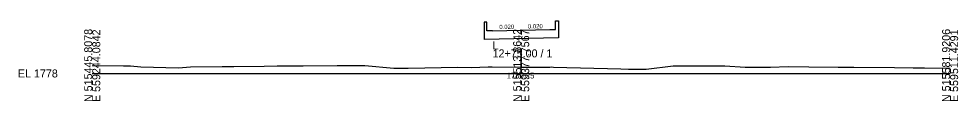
# Model space of a CAD drawing. Extents: x -26 to 1303, y -10 to 9545.
# Drawn here: x -25.7 to 302.8, y 7490.3 to 7518.4 of the extents above; entities that cross this region are included whole.
import ezdxf

# ---------------------------------------------------------------- set-up
doc = ezdxf.new("R2010")
doc.units = 0
for name, color, linetype in [('Exist Cross Section Cell', 7, 'Continuous'), ('Exist XS Center Line Elevation Label', 7, 'Continuous'), ('Exist XS Ground Line', 7, 'Continuous'), ('Prop XS Bridge', 7, 'Continuous'), ('Prop XS Dump Level', 7, 'Continuous'), ('Prop XS SE Text', 7, 'Continuous')]:
    doc.layers.add(name, color=color, linetype=linetype)

msp = doc.modelspace()

# ---------------------------------------------------------------- linework, layer by layer
at = {"layer": 'Exist Cross Section Cell'}
for p, q in [((150, 7500), (150, 7508.43)), ((0, 7500), (150, 7500)), ((150, 7500), (300, 7500))]:
    msp.add_line(p, q, dxfattribs=at)
at = {"layer": 'Exist XS Ground Line'}
for p, q in [((0, 7502.81), (10.9, 7502.62)), ((10.9, 7502.62), (11.85, 7502.63)), ((11.85, 7502.63), (13.37, 7502.67)), ((13.37, 7502.67), (17.03, 7502.37)), ((17.03, 7502.37), (30.18, 7502.03)), ((30.18, 7502.03), (34.39, 7502.38)), ((34.39, 7502.38), (45.4, 7502.41)), ((45.4, 7502.41), (49.52, 7502.46)), ((49.52, 7502.46), (60.12, 7502.59)), ((60.12, 7502.59), (64.72, 7502.63)), ((64.72, 7502.63), (73.71, 7502.7)), ((73.71, 7502.7), (85.63, 7502.74)), ((85.63, 7502.74), (92.47, 7502.77)), ((92.47, 7502.77), (95.27, 7502.76)), ((95.27, 7502.76), (105.43, 7501.81)), ((105.43, 7501.81), (106.79, 7501.84)), ((106.79, 7501.84), (110.44, 7501.91)), ((110.44, 7501.91), (127.84, 7502.25)), ((127.84, 7502.25), (132.57, 7502.13)), ((132.57, 7502.13), (138.4, 7502.27)), ((138.4, 7502.27), (139.9, 7502.27)), ((139.9, 7502.27), (150, 7502.25)), ((150, 7502.25), (160.05, 7502.23)), ((160.05, 7502.23), (160.64, 7502.28)), ((160.64, 7502.28), (161.33, 7502.22)), ((161.33, 7502.22), (184.9, 7501.59)), ((184.9, 7501.59), (187.48, 7501.56)), ((187.48, 7501.56), (190.33, 7501.51)), ((190.33, 7501.51), (193.72, 7501.46)), ((193.72, 7501.46), (203.14, 7502.69)), ((203.14, 7502.69), (208.72, 7502.62)), ((208.72, 7502.62), (212.5, 7502.65)), ((212.5, 7502.65), (215.74, 7502.62)), ((215.74, 7502.62), (221.26, 7502.63)), ((221.26, 7502.63), (228.28, 7502.23)), ((228.28, 7502.23), (232.19, 7502.2)), ((232.19, 7502.2), (237.15, 7502.17)), ((237.15, 7502.17), (243.39, 7502.4)), ((243.39, 7502.4), (250.56, 7502.33)), ((250.56, 7502.33), (260.81, 7502.19)), ((260.81, 7502.19), (266.35, 7502.15)), ((266.35, 7502.15), (280.57, 7502.06)), ((280.57, 7502.06), (287.14, 7501.96)), ((287.14, 7501.96), (291.08, 7501.93)), ((291.08, 7501.93), (300, 7501.87))]:
    msp.add_line(p, q, dxfattribs=at)
at = {"layer": 'Prop XS Bridge'}
for p, q in [((137, 7517.94), (137, 7514.94)), ((138, 7517.94), (137, 7517.94)), ((138, 7514.94), (138, 7517.94)), ((162, 7515.42), (162, 7518.42)), ((162, 7518.42), (163, 7518.42)), ((163, 7518.42), (163, 7515.42)), ((137, 7514.94), (137, 7511.94)), ((140, 7514.98), (138, 7514.94)), ((140, 7514.98), (150, 7515.18)), ((150, 7515.18), (160, 7515.38)), ((160, 7515.38), (162, 7515.42)), ((163, 7515.42), (163, 7512.42)), ((163, 7512.42), (137, 7511.94))]:
    msp.add_line(p, q, dxfattribs=at)
at = {"layer": 'Prop XS Dump Level'}
for p, q in [((140, 7514.98), (150, 7515.18)), ((150, 7515.18), (160, 7515.38))]:
    msp.add_line(p, q, dxfattribs=at)

# ---------------------------------------------------------------- texts
at = {"layer": 'Exist Cross Section Cell'}
for s, p in [('N 515445.8078', (0, 7490)), ('E 559244.0842', (2.8, 7490)), ('N 515513.8642', (150, 7490)), ('E 559377.7567', (152.8, 7490)), ('N 515581.9206', (300, 7490)), ('E 559511.4291', (302.8, 7490))]:
    msp.add_text(s, height=2.8, rotation=90, dxfattribs=at).set_placement(p)
for s, p in [('L', (140, 7508.43)), ('12+75.00 / 1', (140, 7505.63)), ('EL 1778', (-26, 7498.6))]:
    msp.add_text(s, height=2.8, dxfattribs=at).set_placement(p)
at = {"layer": 'Exist XS Center Line Elevation Label'}
msp.add_text('1780.25', height=2, dxfattribs=at).set_placement((144.94, 7498.25))
at = {"layer": 'Prop XS SE Text'}
for p in [(142.38, 7515.53), (152.38, 7515.73)]:
    msp.add_text('0.020', height=1.5, rotation=1.1458, dxfattribs=at).set_placement(p)

doc.saveas('drawing.dxf')
